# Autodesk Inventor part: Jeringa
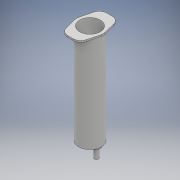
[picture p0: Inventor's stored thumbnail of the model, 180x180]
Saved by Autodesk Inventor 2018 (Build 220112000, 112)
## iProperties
Part Number: Jeringa
Material: Genérico
Document SubType Name: Modeling
Designer: ULISES
Density: 1 g/cm^3
Appearance: Valor por defecto
Author: ULISES
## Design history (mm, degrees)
sketch "Boceto1"
  geometry: C1 r 2 at (0, 0); 1 further point
  constraints: 1 centre point, 1 coincident
  dimensions: "d0" = 4 diameter of C1
extrude "Extrusión1" new body sketch "Boceto1" distance "d1" = 9; taper "d2" = 0 deg
sketch "Boceto2"
  geometry: C1 r 3.5 at (0, 0); 1 further point
  constraints: 1 centre point, 1 coincident
  dimensions: "d3" = 7 diameter of C1
extrude "Extrusión2" join sketch "Boceto2" distance "d4" = 2; taper "d5" = 0 deg
sketch "Boceto3"
  geometry: C1 r 10.5 at (-6, 0); C2 r 3.5 at (0, 0) reference
  constraints: 1 centre point, 1 horizontal alignment
  dimensions: "d6" = 21 diameter of C1; "d26" = 6 distance of C1.centre C2.centre
extrude "Extrusión3" join sketch "Boceto3" distance "d7" = 91.5; taper "d8" = 0 deg
sketch "Boceto4"
  geometry: L1 (12.5, 0)-(8, 18); L2 (8, 18)-(-8, 18); L3 (-8, 18)-(-12.5, 0); L4 (-12.5, 0)-(-8, -18); L5 (-8, -18)-(8, -18); L6 (8, -18)-(12.5, 0); C1 r 10.5 at (0, 0) reference; 2 further points
  constraints: 12 end point, 2 horizontal alignment, 1 coincident, 1 horizontal, 1 parallel, 1 vertical alignment
  dimensions: "d28" = 36 distance between parallel lines of L2 L5; "d29" = 16 distance of L4.end L5.end; "d30" = 16 distance of L1.end L2.end; "d31" = 25 distance of L3.end L1.start; "d32" = 4.5 horizontal distance of L1.start L5.end (= 0.5 x d31 - 0.5 x d29); "d33" = 12.5 distance of C1.centre L1.start (= 0.5 x d31); "d34" = 18 distance from line of L2 C1.centre (= 0.5 x d28)
extrude "Extrusión4" join sketch "Boceto4" distance "d10" = 1.5; taper "d11" = 0 deg
sketch "Boceto5"
  geometry: L1 (0, -10)-(0, 10); L2 (1, -10)-(1, 10); L3 (-1, 10)-(-1, -10); L4 (10, 0)-(-10, 0); L5 (10, 1)-(-10, 1); L6 (-10, -1)-(10, -1); A1 r 1 centre (0, -10) between (-1, -10) and (1, -10); A2 r 1 centre (0, 10) between (1, 10) and (-1, 10); A3 r 1 centre (10, 0) between (10, -1) and (10, 1); A4 r 1 centre (-10, 0) between (-10, 1) and (-10, -1); 3 further points
  constraints: 16 end point, 8 point on circle, 8 tangent, 4 centre point, 2 coincident, 2 midpoint, 2 parallel, 1 horizontal, 1 vertical
  dimensions: "d12" = 20 distance of L1.start L1.end; "d13" = 20 distance of L4.start L4.end; "d14" = 2 distance between parallel lines of L3 L2; "d15" = 2 distance between parallel lines of L6 L5
extrude "Extrusión5" join sketch "Boceto5" distance "d16" = 125; taper "d17" = 0 deg
sketch "Boceto6"
  geometry: C1 r 14 at (0, 0); 1 further point
  constraints: 1 centre point, 1 coincident
  dimensions: "d18" = 28 diameter of C1
extrude "Extrusión6" join sketch "Boceto6" distance "d19" = 1.5; taper "d20" = 0 deg
sketch "Boceto7"
  geometry: C1 r 14 at (0, 0) reference; 1 further point
extrude "Extrusión7" cut sketch "Boceto7" distance "d21" = 125; taper "d22" = 0 deg
sketch "Boceto8"
  geometry: C1 r 9.5 at (-6, 0); A1 r 10.5 centre (-6, 0) between (4.5, 0) and (4.5, 0) reference
  constraints: 1 centre point, 1 coincident
  dimensions: "d27" = 19 diameter of C1
extrude "Extrusión8" cut sketch "Boceto8" distance "d24" = 90; taper "d25" = 0 deg
fillet "Empalme1" dims "d35" = 7
node "Sólido1"
